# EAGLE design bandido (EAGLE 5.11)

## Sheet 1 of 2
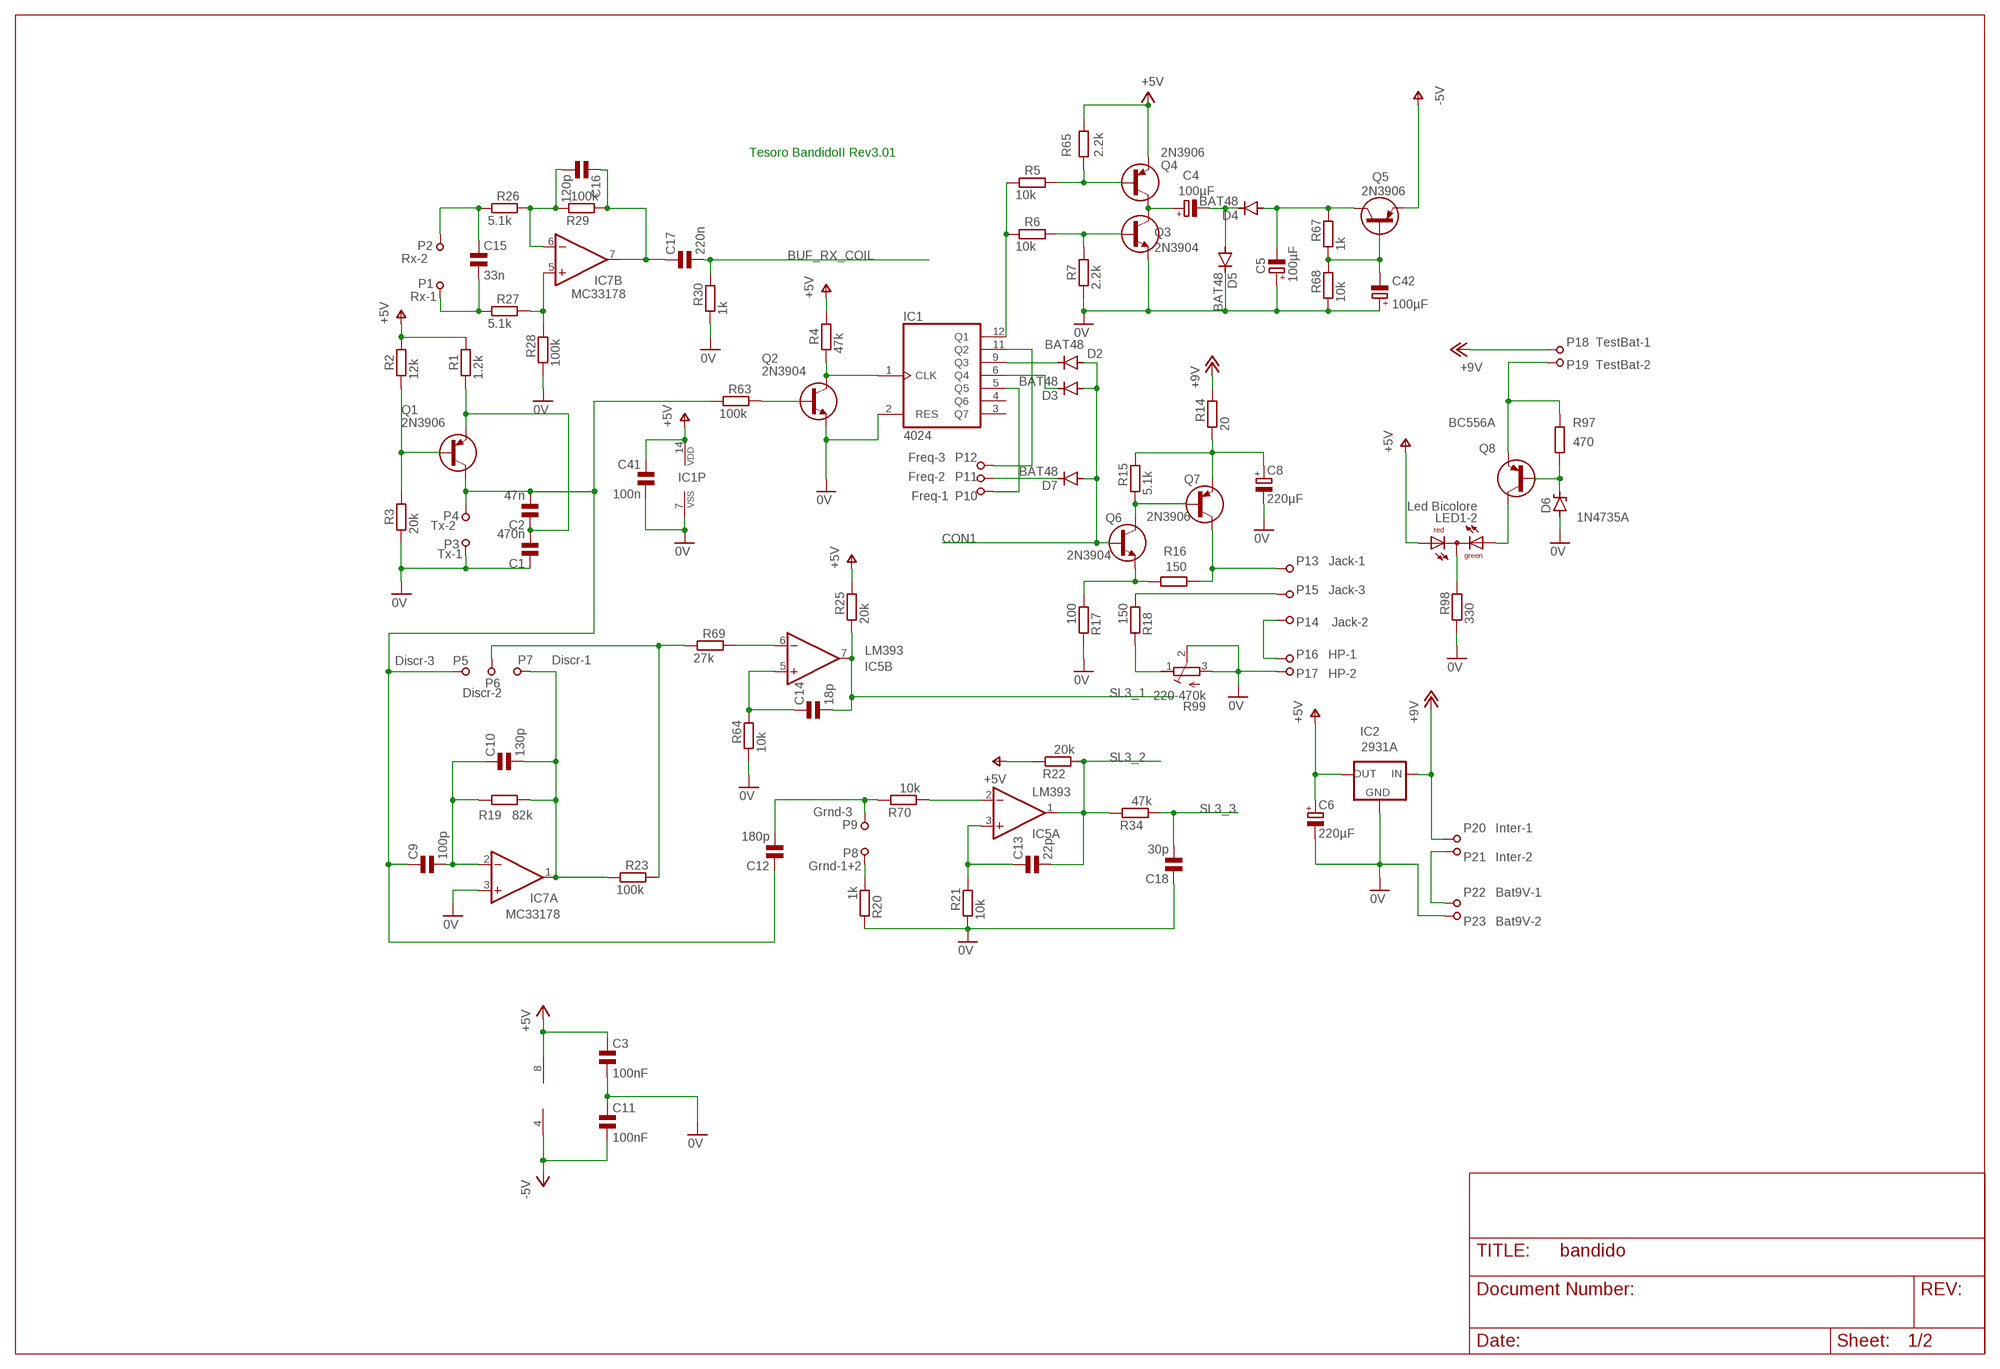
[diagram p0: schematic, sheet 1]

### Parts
C1  470n  WIMA5/3.5  [C5B3.5]
C2  47n  WIMA5/2.5  [C5B2.5]
C3  100nF  WIMA5/2.5  [C5B2.5]
C4  100µF  CHIMIQUESE5-8.5  [E5-8,5]
C5  100µF  CHIMIQUESE2.5-7  [E2,5-7]
C6  220µF  CHIMIQUESE3.5-8  [E3,5-8]
C8  220µF  CHIMIQUESE2.5-7  [E2,5-7]
C9  100p  MICA6-11  [M6-11]
C10  130p  MICA6-11  [M6-11]
C11  100nF  WIMA5/2.5  [C5B2.5]
C12  180p  MICA6-11  [M6-11]
C13  22p  MICA6-11  [M6-11]
C14  18p  MICA6-11  [M6-11]
C15  33n  WIMA5/2.5  [C5B2.5]
C16  120p  MICA6-11  [M6-11]
C17  220n  WIMA5/3  [C5B3]
C18  30p  MICA6-11  [M6-11]
C41  100n  WIMA5/2.5  [C5B2.5]
C42  100µF  CHIMIQUESE2.5-7  [E2,5-7]
D2  BAT48  1N4148DO35-7  [DO35-7]
D3  BAT48  1N4148DO35-7  [DO35-7]
D4  BAT48  1N4148DO35-7  [DO35-7]
D5  BAT48  1N4148DO35-7  [DO35-7]
D6  1N4735A  1N4728  [DO41Z10]
D7  BAT48  1N4148DO35-7  [DO35-7]
IC1  4024  4024N  [DIL14]
IC2  2931A  78XXS  [78XXS]
IC5  LM393  LM393N  [DIL08]
IC7  MC33178  LF442N  [DIL08]
LED1-2  Led Bicolore  DUOLED5MM  [DUOLED5MM]
P1  Rx-1  PICOT_1.9-0.8  [P1.9-0.8]
P2  Rx-2  PICOT_1.9-0.8  [P1.9-0.8]
P3  Tx-1  PICOT_1.9-0.8  [P1.9-0.8]
P4  Tx-2  PICOT_1.9-0.8  [P1.9-0.8]
P5  Discr-3  PICOT_1.9-0.8  [P1.9-0.8]
P6  Discr-2  PICOT_1.9-0.8  [P1.9-0.8]
P7  Discr-1  PICOT_1.9-0.8  [P1.9-0.8]
P8  Grnd-1+2  PICOT_1.9-0.8  [P1.9-0.8]
P9  Grnd-3  PICOT_1.9-0.8  [P1.9-0.8]
P10  Freq-1  PICOT_1.9-0.8  [P1.9-0.8]
P11  Freq-2  PICOT_1.9-0.8  [P1.9-0.8]
P12  Freq-3  PICOT_1.9-0.8  [P1.9-0.8]
P13  Jack-1  PICOT_1.9-0.8  [P1.9-0.8]
P14  Jack-2  PICOT_1.9-0.8  [P1.9-0.8]
P15  Jack-3  PICOT_1.9-0.8  [P1.9-0.8]
P16  HP-1  PICOT_1.9-0.8  [P1.9-0.8]
P17  HP-2  PICOT_1.9-0.8  [P1.9-0.8]
P18  TestBat-1  PICOT_1.9-0.8  [P1.9-0.8]
P19  TestBat-2  PICOT_1.9-0.8  [P1.9-0.8]
P20  Inter-1  PICOT_1.9-0.8  [P1.9-0.8]
P21  Inter-2  PICOT_1.9-0.8  [P1.9-0.8]
P22  Bat9V-1  PICOT_1.9-0.8  [P1.9-0.8]
P23  Bat9V-2  PICOT_1.9-0.8  [P1.9-0.8]
Q1  2N3906  [TO92-EBC]
Q2  2N3904  [TO92-EBC]
Q3  2N3904  [TO92-EBC]
Q4  2N3906  [TO92-EBC]
Q5  2N3906  [TO92-EBC]
Q6  2N3904  [TO92-EBC]
Q7  2N3906  [TO92-EBC]
Q8  BC556A  BC556  [TO92-CBE]
R1  1.2k  RES-EU_0207/7  [0207/7]
R2  12k  RES-EU_0207/7  [0207/7]
R3  20k  RES-EU_0207/7  [0207/7]
R4  47k  RES-EU_0207/7  [0207/7]
R5  10k  RES-EU_0207/7  [0207/7]
R6  10k  RES-EU_0207/7  [0207/7]
R7  2.2k  RES-EU_0207/7  [0207/7]
R14  20  RES-EU_0207/7  [0207/7]
R15  5.1k  RES-EU_0207/7  [0207/7]
R16  150  RES-EU_0207/7  [0207/7]
R17  100  RES-EU_0207/7  [0207/7]
R18  150  RES-EU_0207/7  [0207/7]
R19  82k  RES-EU_0207/7  [0207/7]
R20  1k  RES-EU_0207/7  [0207/7]
R21  10k  RES-EU_0207/7  [0207/7]
R22  20k  RES-EU_0207/7  [0207/7]
R23  100k  RES-EU_0207/7  [0207/7]
R25  20k  RES-EU_0207/7  [0207/7]
R26  5.1k  RES-EU_0207/7  [0207/7]
R27  5.1k  RES-EU_0207/7  [0207/7]
R28  100k  RES-EU_0207/7  [0207/7]
R29  100k  RES-EU_0207/7  [0207/7]
R30  1k  RES-EU_0207/7  [0207/7]
R34  47k  RES-EU_0207/7  [0207/7]
R63  100k  RES-EU_0207/7  [0207/7]
R64  10k  RES-EU_0207/7  [0207/7]
R65  2.2k  RES-EU_0207/7  [0207/7]
R67  1k  RES-EU_0207/7  [0207/7]
R68  10k  RES-EU_0207/7  [0207/7]
R69  27k  RES-EU_0207/7  [0207/7]
R70  10k  RES-EU_0207/7  [0207/7]
R97  470  RES-EU_0207/7  [0207/7]
R98  330  RES-EU_0207/7  [0207/7]
R99  220-470k  R-TRIMMT93YA  [RTRIMT93YA]

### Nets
+12V: IC2.IN P18.P$1 P20.P$1 R14.2 ; supply symbol labelled +9V ; also sheet 2
BUF_RX_COIL: C17.2 R30.2 ; also sheet 2
CON1: D2.A D3.A D7.A Q6.B ; also sheet 2
GND: C1.1 C3.2 C5.+ C6.- C8.- C11.1 C18.P$1 C41.2 C42.+ D5.C D6.A IC1.2(RES) IC1.7(VSS) IC2.GND IC7.3(A:+IN) P3.P$1 P17.P$1 P23.P$1 Q2.E Q3.E R3.1 R7.1 R17.2 R20.2 R21.1 R28.1 R30.1 R64.1 R68.1 R98.1 R99.2(S) R99.3(E) ; supply symbol labelled 0V ; also sheet 2
N$1: C15.2 P1.P$1 R27.1
N$2: IC5.6(B:-IN) R69.2
N$3: Q1.B R2.1 R3.2
N$4: D7.C P11.P$1
N$5: C2.2 C9.P$1 C12.P$1 P4.P$1 P5.P$1 Q1.C R63.1
N$6: C16.P$2 IC7.6(B:-IN) R26.2 R29.2
N$7: C16.P$1 C17.1 IC7.7(B:OUT) R29.1
N$8: IC7.5(B:+IN) R27.2 R28.2
N$9: C9.P$2 C10.P$1 IC7.2(A:-IN) R19.1
N$10: C10.P$2 IC7.1(A:OUT) P7.P$1 R19.2 R23.1
N$11: C14.P$1 IC5.5(B:+IN) R64.2
N$12: P6.P$1 R23.2 R69.1
N$13: C15.1 P2.P$1 R26.1
N$14: C12.P$2 P9.P$1 R70.2
N$15: IC5.2(A:-IN) R70.1
N$16: C13.P$1 IC5.3(A:+IN) R21.2
N$19: P8.P$1 R20.1
N$21: Q2.B R63.2
N$22: IC1.1(CLK) Q2.C R4.1
N$23: C42.- Q5.B R67.1 R68.2
N$24: IC1.11(Q2) P12.P$1
N$25: D2.C IC1.9(Q3)
N$26: D3.C IC1.6(Q4)
N$27: P14.P$1 P16.P$1
N$28: IC1.12(Q1) R5.1 R6.1
N$29: Q4.B R5.2 R65.1
N$30: Q3.B R6.2 R7.2
N$31: C4.+ Q3.C Q4.C
N$32: C5.- D4.A Q5.C R67.2
N$33: Q6.C Q7.B R15.1
N$34: C4.- D4.C D5.A
N$35: C8.+ Q7.E R14.1 R15.2
N$36: Q6.E R16.2 R17.1
N$37: P13.P$1 Q7.C R16.1
N$38: LED1-2.AG Q8.C
N$39: LED1-2.K(C) R98.2
N$40: D6.C Q8.B R97.1
N$41: R18.2 R99.1(A)
N$42: IC1.5(Q5) P10.P$1
N$43: C1.2 C2.1 Q1.E R1.1
N$45: P15.P$1 R18.1
N$46: P21.P$1 P22.P$1
N$47: P19.P$1 Q8.E R97.2
SL3_1: C14.P$2 IC5.7(B:OUT) R25.1 ; also sheet 2
SL3_2: C13.P$2 IC5.1(A:OUT) R22.1 R34.2 ; also sheet 2
SL3_3: C18.P$2 R34.1 ; also sheet 2
V+: C3.1 C6.+ C41.1 IC1.14(VDD) IC2.OUT IC7.8(P:V+) LED1-2.AR Q4.E R1.2 R2.2 R4.2 R22.2 R25.2 R65.2 ; supply symbol labelled +5V ; also sheet 2
V-: C11.2 IC7.4(P:V-) Q5.E ; supply symbol labelled -5V ; also sheet 2
Unconnected: IC1.3(Q7) IC1.4(Q6)

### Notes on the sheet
- Tesoro BandidoII Rev3.01

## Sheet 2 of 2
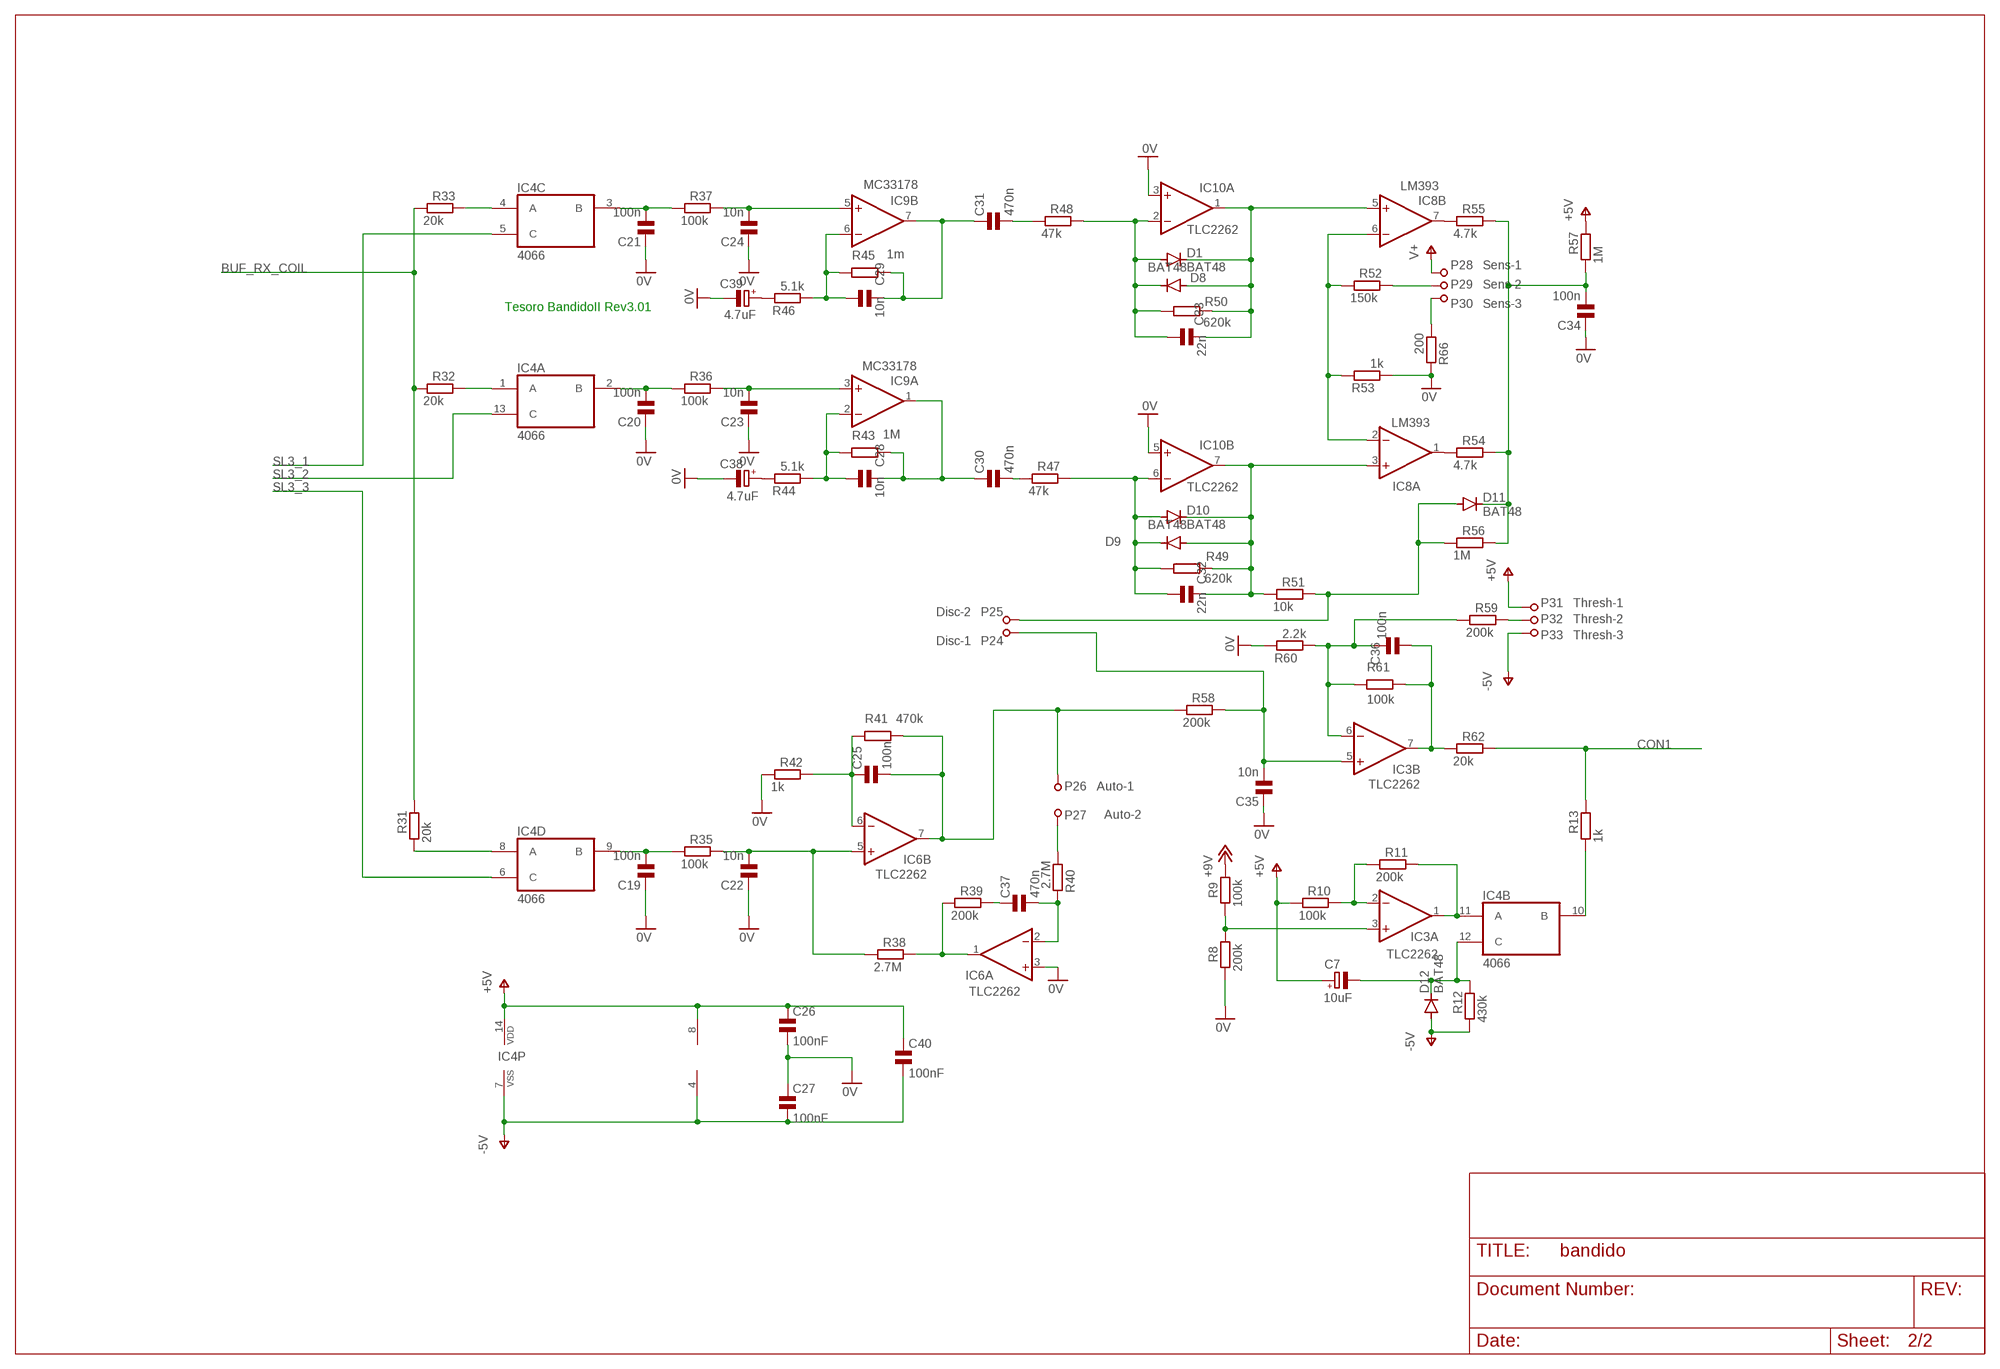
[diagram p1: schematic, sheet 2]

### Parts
C7  10uF  CHIMIQUESE2.5-5  [E2,5-5]
C19  100n  WIMA5/2.5  [C5B2.5]
C20  100n  WIMA5/2.5  [C5B2.5]
C21  100n  WIMA5/2.5  [C5B2.5]
C22  10n  WIMA5/2.5  [C5B2.5]
C23  10n  WIMA5/2.5  [C5B2.5]
C24  10n  WIMA5/2.5  [C5B2.5]
C25  100n  WIMA5/2.5  [C5B2.5]
C26  100nF  WIMA5/2.5  [C5B2.5]
C27  100nF  WIMA5/2.5  [C5B2.5]
C28  10n  WIMA5/2.5  [C5B2.5]
C29  10n  WIMA5/2.5  [C5B2.5]
C30  470n  WIMA5/3.5  [C5B3.5]
C31  470n  WIMA5/3.5  [C5B3.5]
C32  22n  WIMA5/2.5  [C5B2.5]
C33  22n  WIMA5/2.5  [C5B2.5]
C34  100n  WIMA5/2.5  [C5B2.5]
C35  10n  WIMA5/2.5  [C5B2.5]
C36  100n  WIMA5/2.5  [C5B2.5]
C37  470n  WIMA5/3.5  [C5B3.5]
C38  4.7uF  CHIMIQUESE2.5-5  [E2,5-5]
C39  4.7uF  CHIMIQUESE5-8.5  [E5-8,5]
C40  100nF  WIMA5/2.5  [C5B2.5]
D1  BAT48  1N4148DO35-7  [DO35-7]
D8  BAT48  1N4148DO35-7  [DO35-7]
D9  BAT48  1N4148DO35-7  [DO35-7]
D10  BAT48  1N4148DO35-7  [DO35-7]
D11  BAT48  1N4148DO35-7  [DO35-7]
D12  BAT48  1N4148DO35-7  [DO35-7]
IC3  TLC2262  TL062P  [DIL08]
IC4  4066  4016N  [DIL14]
IC6  TLC2262  TL062P  [DIL08]
IC8  LM393  LM393N  [DIL08]
IC9  MC33178  LM358N  [DIL08]
IC10  TLC2262  TL062P  [DIL08]
P24  Disc-1  PICOT_1.9-0.8  [P1.9-0.8]
P25  Disc-2  PICOT_1.9-0.8  [P1.9-0.8]
P26  Auto-1  PICOT_1.9-0.8  [P1.9-0.8]
P27  Auto-2  PICOT_1.9-0.8  [P1.9-0.8]
P28  Sens-1  PICOT_1.9-0.8  [P1.9-0.8]
P29  Sens-2  PICOT_1.9-0.8  [P1.9-0.8]
P30  Sens-3  PICOT_1.9-0.8  [P1.9-0.8]
P31  Thresh-1  PICOT_1.9-0.8  [P1.9-0.8]
P32  Thresh-2  PICOT_1.9-0.8  [P1.9-0.8]
P33  Thresh-3  PICOT_1.9-0.8  [P1.9-0.8]
R8  200k  RES-EU_0207/7  [0207/7]
R9  100k  RES-EU_0207/7  [0207/7]
R10  100k  RES-EU_0207/7  [0207/7]
R11  200k  RES-EU_0207/7  [0207/7]
R12  430k  RES-EU_0207/7  [0207/7]
R13  1k  RES-EU_0207/7  [0207/7]
R31  20k  RES-EU_0207/7  [0207/7]
R32  20k  RES-EU_0207/7  [0207/7]
R33  20k  RES-EU_0207/7  [0207/7]
R35  100k  RES-EU_0207/7  [0207/7]
R36  100k  RES-EU_0207/7  [0207/7]
R37  100k  RES-EU_0207/7  [0207/7]
R38  2.7M  RES-EU_0207/7  [0207/7]
R39  200k  RES-EU_0207/7  [0207/7]
R40  2.7M  RES-EU_0207/7  [0207/7]
R41  470k  RES-EU_0207/7  [0207/7]
R42  1k  RES-EU_0207/7  [0207/7]
R43  1M  RES-EU_0207/7  [0207/7]
R44  5.1k  RES-EU_0207/7  [0207/7]
R45  1m  RES-EU_0207/7  [0207/7]
R46  5.1k  RES-EU_0207/7  [0207/7]
R47  47k  RES-EU_0207/7  [0207/7]
R48  47k  RES-EU_0207/7  [0207/7]
R49  620k  RES-EU_0207/7  [0207/7]
R50  620k  RES-EU_0207/7  [0207/7]
R51  10k  RES-EU_0207/7  [0207/7]
R52  150k  RES-EU_0207/7  [0207/7]
R53  1k  RES-EU_0207/7  [0207/7]
R54  4.7k  RES-EU_0207/7  [0207/7]
R55  4.7k  RES-EU_0207/7  [0207/7]
R56  1M  RES-EU_0207/7  [0207/7]
R57  1M  RES-EU_0207/7  [0207/7]
R58  200k  RES-EU_0207/7  [0207/7]
R59  200k  RES-EU_0207/7  [0207/7]
R60  2.2k  RES-EU_0207/7  [0207/7]
R61  100k  RES-EU_0207/7  [0207/7]
R62  20k  RES-EU_0207/7  [0207/7]
R66  200  RES-EU_0207/7  [0207/7]

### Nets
+12V: R9.2 ; supply symbol labelled +9V ; also sheet 1
BUF_RX_COIL: R31.2 R32.1 R33.1 ; also sheet 1
CON1: R13.2 R62.2 ; also sheet 1
GND: C19.1 C20.1 C21.1 C22.1 C23.1 C24.1 C26.2 C27.1 C34.1 C35.1 C38.- C39.- IC6.3(A:+IN) IC10.3(A:+IN) IC10.5(B:+IN) R8.1 R42.1 R53.1 R60.2 R66.2 ; supply symbol labelled 0V ; also sheet 1
N$17: C31.2 R48.1
N$18: C38.+ R44.2
N$20: C39.+ R46.2
N$48: C19.2 IC4.9(D:B) R35.1
N$49: C22.2 IC6.5(B:+IN) R35.2 R38.1
N$50: C23.2 IC9.3(A:+IN) R36.2
N$51: C20.2 IC4.2(A:B) R36.1
N$52: C21.2 IC4.3(C:B) R37.1
N$53: C24.2 IC9.5(B:+IN) R37.2
N$56: C29.1 IC9.6(B:-IN) R45.1 R46.1
N$57: C29.2 C31.1 IC9.7(B:OUT) R45.2
N$58: C28.1 IC9.2(A:-IN) R43.1 R44.1
N$59: C28.2 C30.1 IC9.1(A:OUT) R43.2
N$61: C30.2 R47.1
N$62: C33.1 D1.A D8.C IC10.2(A:-IN) R48.2 R50.1
N$63: C32.1 D9.C D10.A IC10.6(B:-IN) R47.2 R49.1
N$64: C33.2 D1.C D8.A IC8.5(B:+IN) IC10.1(A:OUT) R50.2
N$65: C32.2 D9.A D10.C IC8.3(A:+IN) IC10.7(B:OUT) R49.2 R51.1
N$66: IC8.2(A:-IN) IC8.6(B:-IN) R52.1 R53.2
N$67: IC8.1(A:OUT) R54.1
N$68: IC8.7(B:OUT) R55.1
N$69: P29.P$1 R52.2
N$70: P30.P$1 R66.1
N$72: C25.1 IC6.6(B:-IN) R41.1 R42.2
N$73: C25.2 IC6.7(B:OUT) P26.P$1 R41.2 R58.1
N$74: IC6.1(A:OUT) R38.2 R39.1
N$75: C37.1 R39.2
N$76: C37.2 IC6.2(A:-IN) R40.2
N$77: C35.2 IC3.5(B:+IN) P24.P$1 R58.2
N$78: C36.2 IC3.7(B:OUT) R61.2 R62.1
N$79: IC3.2(A:-IN) R10.2 R11.1
N$80: IC3.1(A:OUT) IC4.11(B:A) R11.2
N$81: C7.- D12.C IC4.12(B:C) R12.2
N$82: IC3.3(A:+IN) R8.2 R9.1
N$83: IC4.10(B:B) R13.1
N$85: IC4.1(A:A) R32.2
N$86: IC4.8(D:A) R31.1
N$87: IC4.4(C:A) R33.2
N$89: C36.1 IC3.6(B:-IN) R59.1 R60.1 R61.1
N$90: P32.P$1 R59.2
N$91: D11.A P25.P$1 R51.2 R56.1
N$92: P27.P$1 R40.1
N$199: C34.2 D11.C R54.2 R55.2 R56.2 R57.1
SL3_1: IC4.5(C:C) ; also sheet 1
SL3_2: IC4.13(A:C) ; also sheet 1
SL3_3: IC4.6(D:C) ; also sheet 1
V+: C7.+ C26.1 C40.1 IC4.14(P:VDD) IC10.8(P:V+) P28.P$1 P31.P$1 R10.1 R57.2 ; supply symbol labelled +5V ; also sheet 1
V-: C27.2 C40.2 D12.A IC4.7(P:VSS) IC10.4(P:V-) P33.P$1 R12.1 ; supply symbol labelled -5V ; also sheet 1

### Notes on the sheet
- Tesoro BandidoII Rev3.01

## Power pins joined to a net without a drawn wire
V+: IC3.8(P:V+) IC5.8(P:V+) IC6.8(P:V+) IC8.8(P:V+) IC9.8(P:V+)
V-: IC3.4(P:V-) IC5.4(P:V-) IC6.4(P:V-) IC8.4(P:V-) IC9.4(P:V-)

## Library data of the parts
C1-C3 C11 C15 C17 C19-C37 C40 C41 = Condensateurs:WIMA: Condensateurs WIMA MKT, MKS
C4-C8 C38 C39 C42 = Condensateurs:CHIMIQUES: Condensateurs chimiques polarisés, Symbole Européen
C9 C10 C12-C14 C16 C18 = Condensateurs:MICA: Condensateurs SM Mica argentés
D1-D5 D7-D12 = Diodes:1N4148: DIODE
D6 = Diodes:1N4728: DIODE ZENER
IC1 = 40xx:4024: 7-stage binary/ripple COUNTER
IC2 = v-reg:78XXS: VOLTAGE REGULATOR
IC3 IC6 IC10 = CI-lineaire:TL062: OP AMP
IC4 = 40xx:4016: Quad bilateral ANALOG SWITCH
IC5 IC8 = CI-lineaire:LM393: COMPARATOR
IC7 = CI-lineaire:LF442: OP AMP
IC9 = CI-lineaire:LM358: OP AMP also LM158; LM258; LM2904 Source: http://cache.national.com/ds/LM/LM158.pdf
LED1-2 = led:DUOLED5MM: DUO LED 2 colors, 5 mm, round
P1-P33 = Connecteurs:PICOT_: PICOT A SOUDER
Q1 Q4 Q5 Q7 = transistor-pnp:2N3906: PNP Transistor
Q2 Q3 Q6 = transistor-npn:2N3904: NPN Transistor
Q8 = transistor-pnp:BC556*: PNP Transistror
R1-R23 R25-R70 R97 R98 = Resistances:RES-EU_: Résistances
R99 = rcl:R-TRIMM: Trimm resistor

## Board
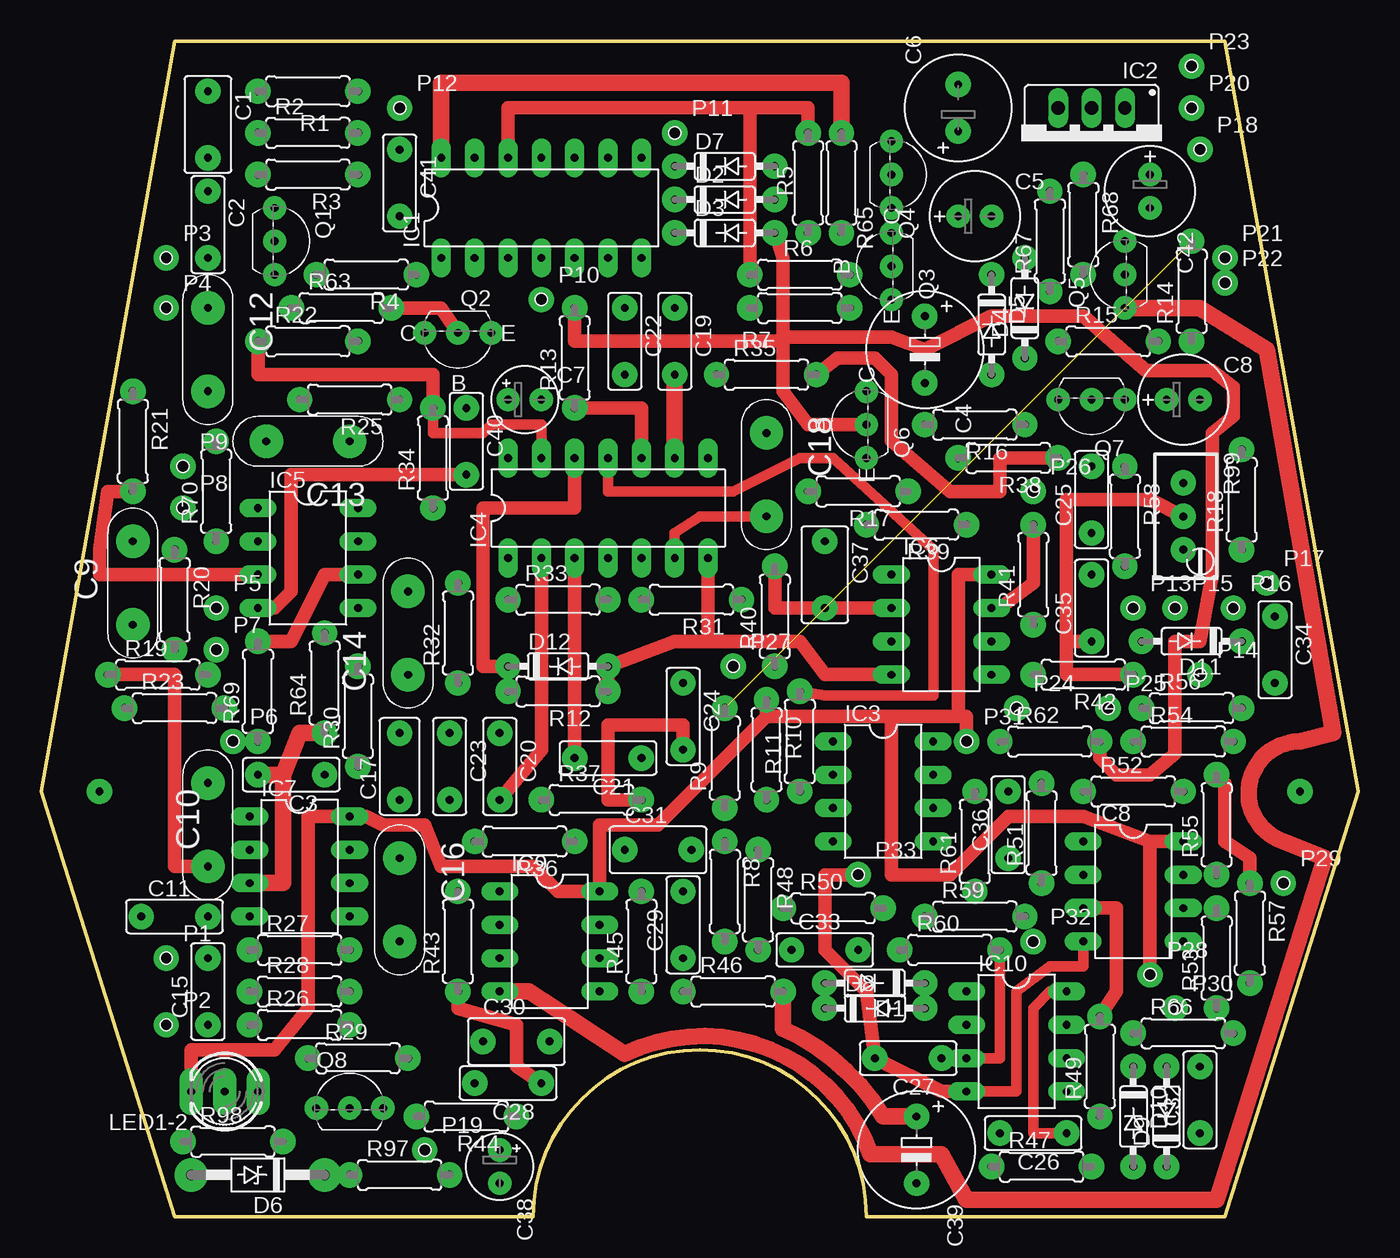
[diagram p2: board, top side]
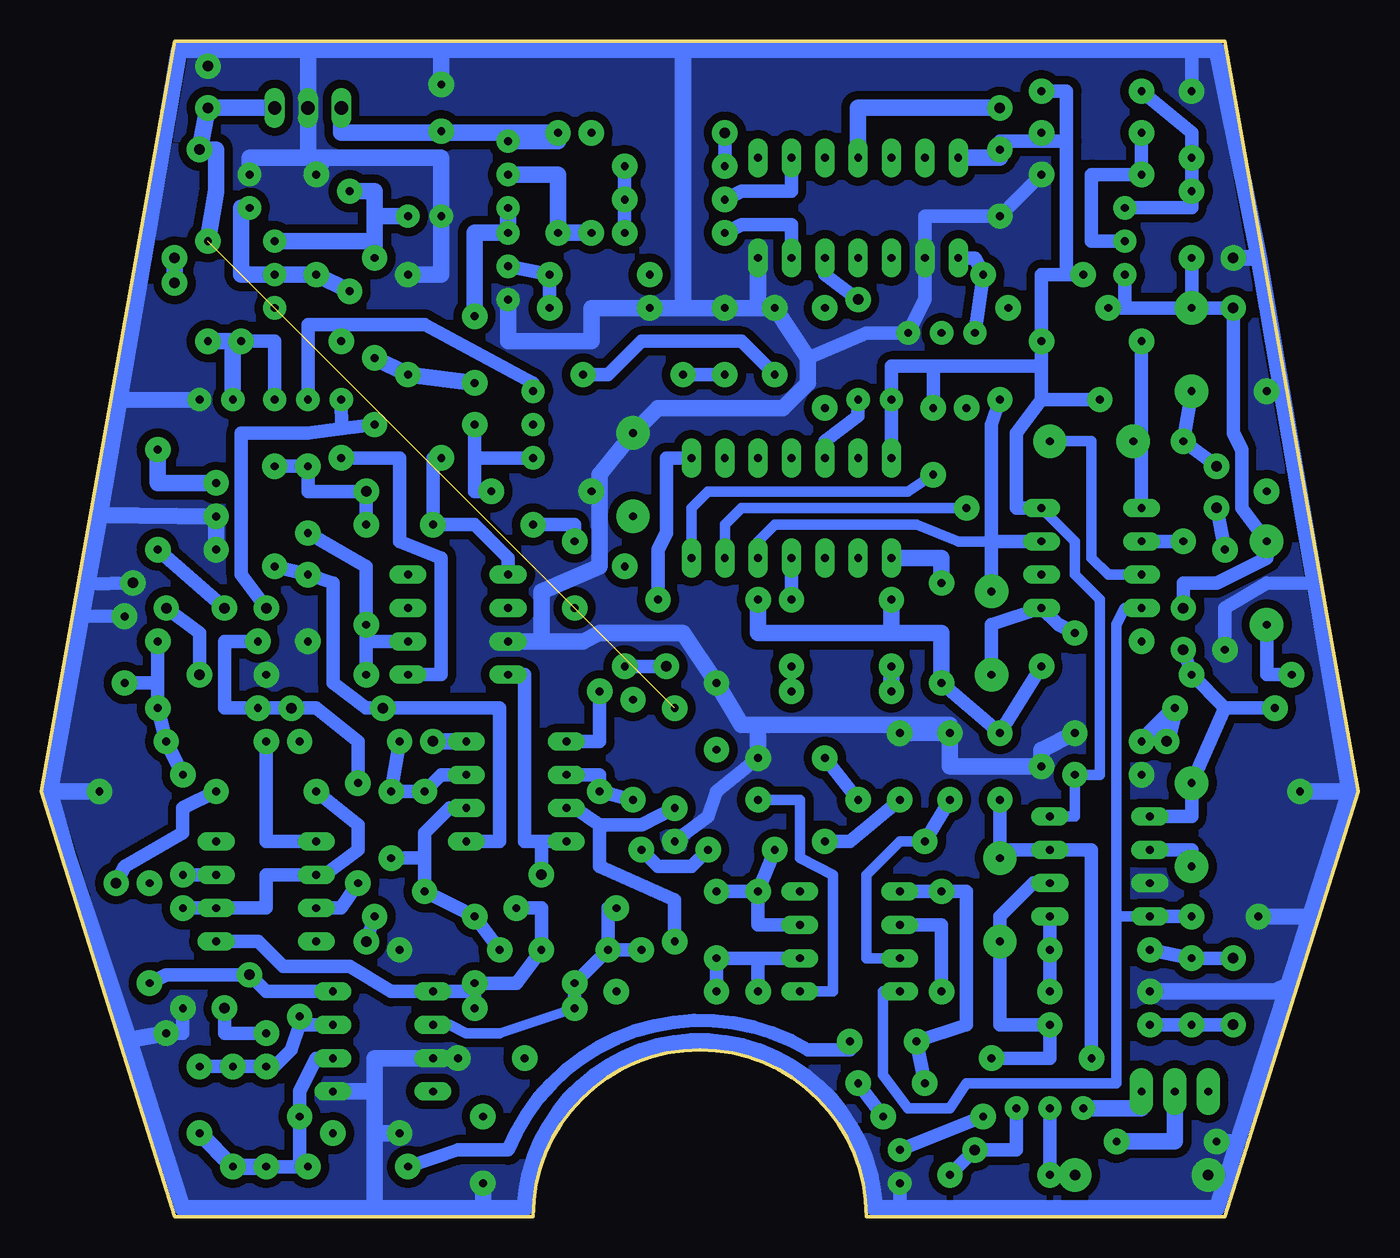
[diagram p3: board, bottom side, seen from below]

Size 100.33 x 89.53 mm. Coordinates in mm from the lower left corner, seen from the top.
Outline: 10.16,0 0,32.38 10.16,89.53 90.17,89.53 100.33,32.38 90.17,0 62.86,0 arc180 37.47,0 10.16,0
Copper layers (1*16): Top 0.035mm / dielectric 1.5mm / Bottom 0.035mm
Design rules "User *": minimum track width 10mil, minimum drill 20mil, track to track 25mil, track to pad 25mil, pad to pad 25mil, via to via 25mil, smd to smd 25mil, copper to edge 40mil, drill to drill 8mil, minimum pad ring 10mil, minimum via ring 8mil, stop-mask expansion 4mil, vias tented up to drill 0mil, thermal gap 10mil

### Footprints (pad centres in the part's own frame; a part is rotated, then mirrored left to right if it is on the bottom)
C5B3.5 = drill 0.6 pad 1.93 round: 1 -2.54,0; 2 2.54,0
C5B2.5 = drill 0.6 pad 1.93 round: 1 -2.54,0; 2 2.54,0
E5-8,5 = drill 0.6 pad 1.93 round: + -2.54,0; - 2.54,0
E2,5-7 = drill 0.6 pad 1.778 round: + -1.27,0; - 1.27,0
E3,5-8 = drill 0.6 pad 1.93 round: + -1.778,0; - 1.778,0
E2,5-5 = drill 0.6 pad 1.778 round: + -1.27,0; - 1.27,0
M6-11 = drill 0.6 pad 2.54 round: P$1 -3.175,0; P$2 3.175,0
C5B3 = drill 0.6 pad 1.93 round: 1 -2.54,0; 2 2.54,0
DO35-7 = drill 0.6 pad 1.93 round: A 3.81,0; C -3.81,0
DO41Z10 = drill 0.8 pad 2.54 round: A 5.08,0; C -5.08,0
DIL14 = drill 0.6 pad 1.5 long: 1 -7.62,-3.81; 2 -5.08,-3.81; 3 -2.54,-3.81; 4 0,-3.81; 5 2.54,-3.81; 6 5.08,-3.81; 7 7.62,-3.81; 8 7.62,3.81; 9 5.08,3.81; 10 2.54,3.81; 11 0,3.81; 12 -2.54,3.81; 13 -5.08,3.81; 14 -7.62,3.81
78XXS = drill 1.016 long: GND 0,-2.54; IN -2.54,-2.54; OUT 2.54,-2.54
DIL08 = drill 0.6 pad 1.422 long: 1 -3.81,-3.81; 2 -1.27,-3.81; 3 1.27,-3.81; 4 3.81,-3.81; 5 3.81,3.81; 6 1.27,3.81; 7 -1.27,3.81; 8 -3.81,3.81
DUOLED5MM = drill 0.6 pad 1.778 long: AG -2.54,0; AR 2.54,0; K 0,0
P1.9-0.8 = drill 0.8 pad 1.93 round: P$1 0,0
TO92-EBC = drill 0.6 pad 1.778 round: B 0,-1.27; C 2.54,-1.27; E -2.54,-1.27
TO92-CBE = drill 0.6 pad 1.778 round: B 0,0; C -2.54,0; E 2.54,0
0207/7 = drill 0.6 pad 1.93 round: 1 -3.81,0; 2 3.81,0
RTRIMT93YA = drill 0.61 pad 1.93 round: 1 0,-2.54; 2 0,0; 3 0,2.54

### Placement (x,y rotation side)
C1  12.7,83.19 270 top
C2  12.7,75.56 270 top
C3  19.05,33.66 180 top
C4  67.31,66.04 270 top
C5  71.12,76.2 0 top
C6  69.85,84.45 90 top
C7  36.83,62.23 0 top
C8  87,62.23 0 top
C9  6.98,48.26 270 top
C10  12.7,29.84 90 top
C11  10.16,22.86 0 top
C12  12.7,66.04 270 top
C13  20.32,59.05 180 top
C14  27.94,44.45 90 top
C15  12.7,17.14 90 top
C16  27.3,24.13 270 top
C17  27.3,34.29 90 top
C18  55.24,56.52 270 top
C19  48.26,66.67 270 top
C20  34.92,34.29 270 top
C21  43.18,34.92 180 top
C22  44.45,66.67 270 top
C23  31.11,34.29 270 top
C24  48.89,38.1 270 top
C25  80.01,54.61 90 top
C26  75.56,6.35 180 top
C27  66.04,12.06 180 top
C28  35.56,10.16 180 top
C29  48.89,22.23 90 top
C30  36.2,13.34 0 top
C31  46.99,27.94 0 top
C32  88.27,8.89 90 top
C33  59.69,20.32 0 top
C34  93.98,43.18 270 top
C35  80.01,46.35 90 top
C36  73.66,29.84 90 top
C37  59.69,48.9 270 top
C38  34.92,3.81 270 top
C39  66.67,5.08 270 top
C40  32.38,59.05 270 top
C41  27.3,78.74 270 top
C42  84.45,78.11 270 top
D1  63.5,17.78 180 top
D2  52.07,77.47 0 top
D3  52.07,74.93 0 top
D4  74.93,69.22 90 top
D5  72.39,67.94 270 top
D6  16.51,3.17 180 top
D7  52.07,80.01 0 top
D8  63.5,15.88 0 top
D9  85.72,7.62 90 top
D10  83.19,7.62 270 top
D11  87.63,43.81 180 top
D12  39.37,41.91 0 top
IC1  38.1,76.83 0 top
IC2  80.01,81.92 180 top
IC3  64.14,32.38 270 top
IC4  43.18,53.98 0 top
IC5  20.32,50.16 270 top
IC6  68.58,45.09 270 top
IC7  19.68,26.67 270 top
IC8  83.19,24.77 270 top
IC9  38.73,20.95 270 top
IC10  74.3,13.34 270 top
LED1-2  13.97,9.53 180 top
P1  9.52,19.68 0 top
P2  9.52,14.61 0 top
P3  9.52,73.03 0 top
P4  9.52,69.22 0 top
P5  13.34,46.35 0 top
P6  14.6,36.2 0 top
P7  13.34,43.18 0 top
P8  10.8,53.98 0 top
P9  10.8,57.15 0 top
P10  38.1,69.85 0 top
P11  48.26,82.55 0 top
P12  27.3,84.45 0 top
P13  83.19,46.35 0 top
P14  88.27,41.27 0 top
P15  86.36,46.35 0 top
P16  90.81,46.35 0 top
P17  93.34,48.26 0 top
P18  88.27,81.28 0 top
P19  29.21,5.08 0 top
P20  87.63,84.45 0 top
P21  90.17,73.03 0 top
P22  90.17,71.12 0 top
P23  87.63,87.63 0 top
P24  74.3,38.73 0 top
P25  81.28,38.73 0 top
P26  75.56,55.24 0 top
P27  52.7,41.91 0 top
P28  84.45,18.41 0 top
P29  94.62,25.4 0 top
P30  86.36,15.88 0 top
P31  70.48,36.2 0 top
P32  75.56,20.95 0 top
P33  62.23,26.04 0 top
Q1  19.05,74.3 270 top
Q2  31.75,66.04 180 top
Q3  63.5,72.39 90 top
Q4  66.04,79.38 270 top
Q5  81.28,71.75 90 top
Q6  61.59,60.33 90 top
Q7  80.01,60.96 180 top
Q8  23.49,8.26 0 top
R1  20.32,85.72 0 top
R2  20.32,82.55 0 top
R3  20.32,79.38 180 top
R4  24.77,71.75 180 top
R5  58.42,78.74 270 top
R6  57.78,71.75 0 top
R7  57.78,69.22 0 top
R8  52.07,24.77 270 top
R9  52.07,34.92 90 top
R10  55.24,35.56 270 top
R11  57.78,36.2 90 top
R12  39.37,40.01 180 top
R13  40.64,65.41 90 top
R14  87.63,70.48 90 top
R15  81.28,66.67 0 top
R16  71.12,60.33 180 top
R17  62.23,55.24 180 top
R18  91.44,54.61 90 top
R19  8.89,41.27 0 top
R20  10.16,46.99 270 top
R21  6.98,59.05 270 top
R22  20.32,66.67 0 top
R23  10.16,38.73 0 top
R25  23.49,62.23 180 top
R26  19.68,14.61 0 top
R27  19.68,20.32 0 top
R28  19.68,17.14 0 top
R29  24.13,12.06 0 top
R30  24.13,38.1 90 top
R31  49.53,46.99 180 top
R32  31.75,44.45 90 top
R33  39.37,46.99 0 top
R34  29.84,57.78 90 top
R35  55.24,64.14 0 top
R36  36.83,28.57 180 top
R37  41.91,31.75 0 top
R38  73.66,57.78 180 top
R39  66.67,52.7 180 top
R40  55.88,45.72 90 top
R41  75.56,48.9 90 top
R42  79.38,41.27 180 top
R43  31.75,20.95 90 top
R44  32.38,7.62 180 top
R45  45.72,20.95 90 top
R46  52.7,17.14 0 top
R47  76.2,3.81 0 top
R48  54.61,24.13 270 top
R49  80.64,11.43 90 top
R50  60.33,23.5 0 top
R51  76.2,29.21 90 top
R52  83.19,32.38 0 top
R53  89.53,19.68 90 top
R54  87,36.2 0 top
R55  89.53,29.84 90 top
R56  87.63,38.73 0 top
R57  92.07,21.59 270 top
R58  82.55,53.34 270 top
R59  71.12,22.86 0 top
R60  69.22,20.32 0 top
R61  71.12,28.57 90 top
R62  76.84,36.2 0 top
R63  22.86,69.22 0 top
R64  21.59,40.64 90 top
R65  60.96,78.74 90 top
R66  87,13.97 0 top
R67  76.84,74.3 90 top
R68  79.38,75.56 270 top
R69  16.51,40.01 90 top
R70  13.34,55.24 90 top
R97  27.3,3.17 0 top
R98  14.6,5.71 0 top
R99  87,53.34 180 top

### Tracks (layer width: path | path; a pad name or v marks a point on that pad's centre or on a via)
+12V  (1 unrouted)
  Bottom 1.27: IC2.IN P20.P$1 P18.P$1 87,81.28 87,78.11 R14.2
BUF_RX_COIL
  Bottom 1.016: R30.2 C17.2 R32.1
  Bottom 1.27: R31.2 45.72,44.45 35.56,44.45 | 35.56,44.45 31.75,44.45 R32.1 | 35.56,44.45 R33.1
CON1
  Top 1.016: 56.52,66.67 56.52,62.87 58.42,60.33 Q6.B | 56.52,66.67 56.52,66.99 | 56.52,66.99 56.52,73.03 D3.A | R13.2 40.64,66.67 56.52,66.67 | R62.2 80.64,34.92 81.91,33.66 84.45,33.66 86.36,35.24 86.36,43.81 88.27,43.81 89.22,48.9 89.22,59.69 90.81,60.96 90.81,63.18 89.22,64.45 84.14,64.45 79.38,68.58 72.39,68.58 67.31,66.04 64.77,66.99 56.52,66.99
  Bottom 1.016: D7.A D2.A D3.A
GND  (via drill 0.6 pad 1.93)
  Top 0.813: R60.2 73.03,12.06 IC10.3
  Top 1.016: R42.1 78.11,41.27 78.11,43.81 | 78.11,43.81 78.11,54.61 84.45,54.61 R99.2 | 78.11,43.81 C35.1
  Top 1.27: C3.2 18.41,33.66 | 18.41,33.66 18.41,25.4 IC7.3 | R64.1 19.68,36.83 18.41,33.66
  Bottom 1.016: 12.7,88.9 C1.1 | 34.92,0.64 C38.- | C21.1 48.89,32.38 49.53,30.48 R8.1 | R53.1 89.53,13.97 R66.2 | 97.27,45.74 C34.1 | 96.82,48.2 P17.P$1 | R20.2 10.16,46.35 6.98,48.26 3.34,48.23 | R3.1 C41.2 33.02,76.2 IC1.2 33.02,69.85 Q2.E 37.47,67.31 41.91,65.41
  Bottom 1.27: 80.01,80.64 IC2.GND 80.01,88.9 | 80.01,80.64 78.74,80.64 | 78.74,80.64 69.85,80.64 C5.+ 69.85,71.75 D5.C | Q3.E 64.77,66.67 58.42,66.67 58.42,69.22 R7.1 51.44,69.22 | 80.01,80.64 84.45,80.64 C42.+ | 69.85,88.9 80.01,88.9 | 69.85,88.9 C6.- | 51.44,69.22 C19.1 45.72,69.22 | 45.72,69.22 C22.1 41.91,65.41 41.91,63.5 43.81,61.59 53.34,61.59 C18.P$1 57.78,56.52 57.78,55.24 | 45.72,69.22 IC1.7 | C23.1 31.11,34.29 R30.1 24.13,35.56 R64.1 | C23.1 31.11,37.47 45.72,37.47 | 45.72,37.47 46.99,37.47 C24.1 51.44,44.45 57.78,44.45 59.05,43.81 62.23,43.81 | 45.72,37.47 C21.1 | C23.1 C20.1 | 66.67,0.64 63.5,0.64 arc175 36.83,0.64 34.92,0.64 10.8,0.64 10,3.12 | 66.67,0.64 74.93,0.64 | 74.93,0.64 89.53,0.64 93.63,13.45 | 57.78,55.24 R17.2 | 57.78,55.24 57.78,49.53 62.23,47.62 62.23,43.81 | 93.63,13.45 94,14.6 98.18,27.18 99.69,32.38 | 95.87,53.45 96.82,48.2 97.13,46.47 97.27,45.74 98.89,36.8 99.69,32.38 | 95.87,53.45 94.38,62.19 | 94.38,62.19 89.84,88.84 | 95.87,53.45 R99.2 R99.3 | 93.63,13.45 R66.2 | 66.67,0.64 C39.- | 62.23,43.81 IC6.3 | 74.93,0.64 74.93,6.35 | 74.93,6.35 74.93,9.53 | 74.93,9.53 74.93,12.06 IC10.3 C27.1 | 74.93,9.53 IC10.5 | 74.93,6.35 C26.2 | 78.74,80.64 R68.1 | 51.44,88.9 12.7,88.9 10.8,88.9 7.56,73.03 | 51.44,69.22 51.44,88.9 | 51.44,88.9 69.85,88.9 | 7.56,73.03 5.83,62.85 | 5.83,62.85 3.34,48.23 0.63,32.38 | 0.63,32.38 3.7,22.82 | 3.7,22.82 5.35,17.66 | 5.35,17.66 9.2,5.61 | 9.2,5.61 10,3.12 | 10,3.12 D6.A | 9.2,5.61 R98.1 | 7.56,73.03 P3.P$1 | 5.83,62.85 R21.1 | 3.7,22.82 C11.1 | R28.1 6.35,17.14 5.35,17.66 | 0.63,32.38 v4.45,32.38 | 99.69,32.38 v95.88,32.38 | 94.38,62.19 C8.- | 80.01,88.9 87.63,88.9 | 87.63,88.9 89.53,88.9 | 87.63,88.9 P23.P$1
  pour Bottom (no thermals): 10.16,89.53 90.17,89.53 100.33,32.38 90.17,0 10.16,0 0,32.38
N$1
  Bottom 1.016: R27.1 C15.2 P1.P$1
N$2
  Top 1.016: IC5.6 21.59,48.9 19.05,43.81 R69.2
N$3
  Bottom 1.016: Q1.B 20.32,74.3 20.32,79.38 R3.2 R2.1
N$4
  Bottom 1.016: D7.C P11.P$1
N$5
  Bottom 1.016: C12.P$1 P4.P$1 9.52,59.69 8.89,58.42 8.89,53.98 C9.P$1 6.98,50.16 10.8,48.26 13.34,48.26 P5.P$1 | C12.P$1 C2.2 | C12.P$1 17.78,69.22 | 17.78,69.22 R63.1 | 17.78,69.22 Q1.C
N$6
  Bottom 1.016: R29.2 23.49,12.06 R26.2 27.3,14.61 C16.P$2 27.3,22.86 24.77,25.4 IC7.6
N$7
  Bottom 1.016: 27.3,27.94 C16.P$1 | 27.3,27.94 C17.1 | 27.3,27.94 IC7.7 20.32,27.94 R29.1
N$8
  Bottom 1.016: R28.2 R27.2 IC7.5
N$9
  Top 1.016: R19.1 10.16,41.27 10.16,26.67 C10.P$1
  Bottom 1.016: IC7.2 12.7,27.94 C10.P$1 | C9.P$2 6.98,41.27 R19.1
N$10
  Bottom 1.016: IC7.1 12.7,30.48 C10.P$2 10.16,38.73 | P7.P$1 R19.2 10.16,38.73 | 10.16,38.73 R23.1
N$11
  Bottom 1.016: C14.P$1 27.94,45.09 IC5.5 22.86,45.09 R64.2
N$12
  Bottom 1.27: R69.1 R23.2 P6.P$1
N$13
  Bottom 1.016: R26.1 C15.1 P2.P$1
N$14
  Bottom 1.016: C12.P$2 R70.2 P9.P$1
N$15
  Bottom 1.016: R70.1 IC5.2
N$16
  Top 1.016: R21.2 5.08,55.24 4.45,50.8 4.45,48.9 IC5.3
  Bottom 0.813: IC5.3 19.05,48.9 20.32,50.16 20.32,59.05 C13.P$1
N$17
  Bottom 1.016: R48.1 53.34,26.67 50.8,26.67 C31.2
N$18
  Bottom 1.016: C38.+ R44.2
N$19
  Bottom 1.016: R20.1 P8.P$1
N$20
  Top 1.27: C39.+ 64.14,7.62 arc35 56.52,14.29 R46.2
N$21
  Top 1.016: R63.2 30.48,69.22 Q2.B
N$22
  Bottom 1.016: Q2.C R4.1 29.21,73.03 IC1.1
N$23
  Bottom 1.27: C42.- 85.09,76.83 85.09,71.75 Q5.B R68.2 R67.1
N$24
  Bottom 1.27: P12.P$1 38.1,84.45 IC1.11
N$25
  Bottom 1.016: IC1.9 43.18,78.11 46.99,78.11 D2.C
N$26
  Bottom 1.016: IC1.6 43.18,75.56 46.99,75.56 D3.C
N$27
  Bottom 1.016: P16.P$1 88.27,44.45 P14.P$1
N$28
  Top 1.016: IC1.12 35.56,84.45 53.98,84.45 | 53.98,84.45 58.42,84.45 R5.1 | 53.98,84.45 R6.1
N$29
  Bottom 1.27: R5.2 R65.1 60.96,79.38 Q4.B
N$30
  Bottom 1.016: Q3.B R6.2 R7.2
N$31
  Bottom 1.27: C4.+ 67.31,74.93 Q3.C Q4.C
N$32
  Bottom 1.27: 74.93,76.2 C5.- | D4.A 74.93,74.3 | 74.93,74.3 74.93,76.2 | R67.2 74.93,78.11 74.93,76.2 | 74.93,74.3 Q5.C
N$33
  Bottom 1.016: Q6.C 62.86,63.5 71.12,67.94 77.47,67.94 | 77.47,67.94 80.01,67.94 Q7.B | 77.47,67.94 R15.1
N$34
  Bottom 1.27: D4.C D5.A C4.-
N$35
  Bottom 1.016: Q7.E 82.55,66.67 R15.2
  Bottom 1.27: R15.2 85.72,66.67 | 85.72,66.67 R14.1 | 85.72,66.67 C8.+
N$36
  Bottom 1.016: 67.31,57.78 67.31,55.24 R17.1 | 67.31,57.78 R16.2 | 67.31,57.78 Q6.E
N$37
  Bottom 1.016: 77.43,60.01 R16.1 | 77.43,60.01 80.01,59.69 85.09,59.69 85.09,48.9 P13.P$1 | 77.43,60.01 Q7.C
N$38
  Bottom 1.27: LED1-2.AG 16.51,8.26 Q8.C
N$39
  Bottom 1.27: LED1-2.K 13.97,5.71 R98.2
N$40
  Bottom 1.016: Q8.B R97.1 D6.C
N$41
  Bottom 1.27: R18.2 91.44,55.88 R99.1
N$42
  Bottom 1.016: P10.P$1 40.64,71.75 IC1.5
N$43
  Bottom 1.016: Q1.E 12.7,76.83 C2.1 C1.2 12.7,82.55 R1.1
N$45
  Bottom 1.016: P15.P$1 R18.1
N$46
  Bottom 1.27: P22.P$1 P21.P$1
N$47
  Bottom 1.016: R97.2 P19.P$1 26.04,5.08 Q8.E
N$48
  Top 1.27: IC4.9 C19.2
  Bottom 1.016: C19.2 R35.1
N$49
  Top 1.016: R35.2 60.64,65.41 63.5,65.41 64.77,64.14 64.77,59.05 69.22,55.24 73.03,55.24 73.03,57.78 R38.1
  Bottom 1.016: C22.2 46.99,66.67 54.61,66.67 57.15,64.14 R35.2 | R38.1 73.03,57.78 73.03,51.44 69.85,50.16 69.85,41.27 IC6.5
N$50
  Bottom 0.813: IC9.3 37.47,19.68 37.47,26.04 34.92,28.57 R36.2
  Bottom 1.016: R36.2 C23.2
N$51
  Top 1.016: IC4.2 38.1,35.56 C20.2
  Bottom 1.016: C20.2 38.73,28.57 R36.1
N$52
  Top 1.016: C21.2 IC4.3
  Bottom 1.016: R37.1 C21.2
N$53
  Top 1.016: C24.2 48.89,37.47 43.18,37.47 43.18,31.75 R37.2
  Bottom 0.813: IC9.5 40,17.14 40,26.04 42.55,27.3 42.55,31.75 R37.2
N$56
  Bottom 1.016: IC9.6 45.72,19.68 | 45.72,19.68 C29.1 R46.1 | 45.72,19.68 R45.1
N$57
  Bottom 1.016: IC9.7 45.72,22.23 R45.2 | R45.2 C31.1 | R45.2 C29.2
N$58
  Top 1.016: R43.1 31.75,15.88 36.2,14.61 36.2,11.43 C28.1
  Bottom 1.016: IC9.2 31.75,22.23 R43.1 | C28.1 R44.1
N$59
  Bottom 1.016: IC9.1 R43.2 29.84,24.77 29.84,14.61 C30.1 C28.2
N$61
  Bottom 1.016: R47.1 68.58,5.08 64.77,5.08 arc99 41.91,12.7 38.73,12.7 C30.2
N$62
  Bottom 0.813: D8.C 65.41,13.97 67.94,13.97 69.22,14.61 IC10.2
  Bottom 1.016: D8.C D1.A C33.1 | R48.2 C33.1 | C33.1 57.15,23.5 R50.1
N$63
  Bottom 1.016: IC10.6 79.38,12.06 80.64,9.53 R49.1 80.64,3.81 | 80.64,3.81 D10.A | R47.2 80.64,3.81
  Bottom 1.27: C32.1 D9.C D10.A
N$64
  Bottom 1.016: 67.31,17.14 D1.C 64.14,17.78 C33.2 62.23,23.5 R50.2 | 67.31,17.14 IC10.1 73.66,17.14 76.84,19.05 81.91,19.05 83.82,20.95 IC8.5 | D8.A 67.31,17.14
N$65
  Top 1.016: IC8.3 81.91,23.5 81.91,17.14 R49.2
  Bottom 1.016: C32.2 D9.A D10.C 82.55,11.43 81.28,12.7 80.64,14.61 | 80.64,14.61 R49.2 | IC8.3 77.47,23.5 R51.1 | IC10.7 80.64,14.61
N$66
  Bottom 1.016: R53.2 IC8.6 83.19,23.5 83.19,26.04 IC8.2 78.74,26.04 76.2,27.94 76.2,29.84 R52.1
N$67
  Bottom 1.016: IC8.1 83.19,28.57 R54.1
N$68
  Bottom 1.016: IC8.7 R55.1
N$69
  Bottom 1.016: R52.2 89.53,31.11 89.53,29.21 93.98,26.67 P29.P$1
N$70
  Bottom 1.016: R66.1 86.36,13.97 P30.P$1
N$72
  Bottom 1.016: 75.56,43.81 R42.2 | 75.56,43.81 R41.1 75.56,49.53 C25.1 | IC6.6 75.56,43.81
N$73
  Top 1.016: R41.2 75.56,48.26 73.03,46.35 IC6.7
  Bottom 1.016: R41.2 P26.P$1 80.01,55.24 C25.2 R58.1
N$74
  Bottom 1.016: R38.2 70.48,57.78 R39.1 67.31,52.7 64.77,50.16 IC6.1
N$75
  Bottom 1.016: R39.2 59.69,52.7 C37.1
N$76
  Top 1.016: R40.2 55.88,46.35 C37.2 IC6.2
N$77
  Bottom 1.016: R58.2 C35.2 78.11,48.26 78.11,40.64 75.56,38.73 P24.P$1 65.41,38.73 65.41,28.57 IC3.5
N$78
  Bottom 1.016: IC3.7 69.85,33.66 R61.2 C36.2 R62.1
N$79
  Bottom 1.016: IC3.2 57.78,33.66 R11.1 R10.2
N$80
  Top 0.813: R11.2 59.69,39.69 67.94,39.69 67.94,50.8 60.33,57.78 57.78,57.78 52.7,55.24 43.18,55.24 IC4.11
  Bottom 1.016: R11.2 57.78,36.2 IC3.1
N$81
  Top 1.016: D12.C 33.66,41.91 33.66,53.98 40.64,53.98 IC4.12
  Bottom 1.016: IC4.12 40.64,59.05 38.1,60.96 C7.-
  Bottom 1.27: R12.2 D12.C
N$82
  Bottom 1.016: IC3.3 59.69,31.11 57.78,29.84 | 57.78,29.84 57.78,26.67 52.07,24.13 R8.2 | R9.1 54.61,29.84 57.78,29.84
N$83
  Top 1.016: R13.1 45.72,61.59 IC4.10
N$85
  Bottom 1.27: IC4.1 31.75,50.16 R32.2
N$86
  Bottom 1.016: IC4.8 52.7,57.78 52.7,52.07 53.34,50.8 R31.1
N$87
  Bottom 1.016: R33.2 IC4.4
N$89
  Bottom 1.016: IC3.6 69.22,31.11 71.12,29.21 71.12,27.3 | 71.12,27.3 R61.1 R59.1 R60.1 | 71.12,27.3 C36.1
N$90
  Bottom 1.016: P32.P$1 R59.2
N$91
  Bottom 1.016: D11.A 86.36,43.81 86.36,38.73 R56.1 P25.P$1 79.38,38.73 76.2,36.2 R51.2
N$92
  Bottom 1.016: P27.P$1 R40.1
N$199
  Top 1.016: R55.2 90.17,33.02 90.17,28.57 92.07,27.3 R57.1
  Bottom 1.016: 91.44,40.64 R56.2 R54.2 R55.2 | 91.44,40.64 D11.C | 91.44,40.64 C34.2
SL3_1
  Bottom 0.813: 27.94,51.44 30.48,51.44 33.66,52.7 44.45,52.7 45.72,51.44 IC4.5
  Bottom 1.016: 27.94,51.44 C14.P$2 | 27.94,51.44 27.94,60.33 R25.1 | IC5.7 27.94,51.44
SL3_2
  Top 0.813: R34.2 29.84,59.69 33.66,59.69 34.29,60.33 38.1,60.33 IC4.13
  Top 1.016: R34.2 29.84,64.14 16.51,64.14 R22.1
  Bottom 1.016: IC5.1 16.51,59.05 | 16.51,59.05 C13.P$2 | 16.51,59.05 R22.1
SL3_3
  Top 0.813: C18.P$2 50.16,53.34 48.26,52.07 IC4.6
  Bottom 0.813: R34.1 46.99,53.98 48.26,52.7 IC4.6
V+
  Top 0.813: C26.1 75.56,6.35 75.56,15.88 76.84,17.14 IC10.8
  Top 1.016: IC6.8 69.85,48.9 69.85,38.1 | 84.45,28.57 IC8.8 | 84.45,28.57 79.38,30.48 73.66,30.48 69.22,26.04 64.77,26.04 64.77,38.1 | 55.24,38.1 46.99,29.84 42.55,29.84 IC9.8 39.37,24.77 37.47,26.67 30.48,26.67 29.21,29.84 26.04,29.84 24.77,30.48 IC7.8 20.32,30.48 20.32,15.88 17.78,12.7 11.43,12.7 LED1-2.AR | 55.24,38.1 64.77,38.1 | 64.77,38.1 69.85,38.1 | 55.24,38.1 R10.1 | 84.45,28.57 P28.P$1 | P31.P$1 70.48,38.1 69.85,38.1
  Top 1.27: IC1.14 30.48,86.36 60.96,86.36 R65.2
  Bottom 0.813: IC5.8 21.59,51.44 21.59,48.9 19.68,46.99 19.68,33.66 C3.1 21.59,30.48 IC7.8
  Bottom 1.016: IC5.8 26.04,53.98 26.04,59.69 24.13,62.23 | 24.13,62.23 R25.2 | 24.13,64.77 R22.2 24.13,71.75 22.22,71.75 | C41.1 27.3,81.92 24.13,81.92 | IC10.8 83.19,17.14 P28.P$1 90.81,18.41 R57.2 | 22.22,71.75 R4.2 | 24.13,64.77 32.38,64.77 | 32.38,64.77 35.56,64.77 C7.+ IC4.14 | 32.38,64.77 C40.1 | 22.22,81.92 24.13,81.92 | 24.13,81.92 R2.2 | 22.22,71.75 22.22,81.92 | R1.2 22.22,85.72 22.22,81.92 | 24.13,62.23 24.13,64.77
  Bottom 1.27: IC2.OUT 77.47,82.55 70.48,82.55 C6.+ 69.22,82.55 R65.2 60.96,81.92 Q4.E | IC1.14 27.3,80.64 C41.1 | IC3.8 P31.P$1
V-
  Top 0.813: IC8.4 79.38,19.05 76.84,19.05 74.3,17.14 74.3,9.53 IC10.4
  Top 1.016: IC6.4 59.69,41.27 57.78,43.81 50.8,43.81 | IC5.4 17.78,46.35 19.05,47.62 19.05,56.52 C40.2 | IC10.4 68.58,9.53 C27.2 62.86,17.14 59.69,20.32 59.69,26.04 P33.P$1 | 50.8,43.81 48.26,43.81 D12.A R12.1 | IC4.7 50.8,43.81
  Top 1.27: Q5.E 88.27,69.22 93.34,66.04 98.42,36.83 95.88,36.2 arc161 94.62,28.57 97.79,27.3 89.53,1.27 70.48,1.27 68.58,4.76 63.18,4.76 arc96 44.45,12.38 37.15,17.14 IC9.4
  Bottom 0.813: IC5.4 17.78,46.35 18.41,45.09 18.41,22.86 | 18.41,22.86 IC7.4 | IC9.4 36.2,17.14 36.2,10.79 34.29,8.26 31.11,8.26 29.84,10.16 18.41,10.16 18.41,22.86 | IC4.7 50.8,53.98 49.53,55.24 34.29,55.24 C40.2
  Bottom 1.016: IC6.4 63.5,41.27 63.5,28.57 IC3.4 62.23,28.57 P33.P$1 | IC7.4 C11.2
